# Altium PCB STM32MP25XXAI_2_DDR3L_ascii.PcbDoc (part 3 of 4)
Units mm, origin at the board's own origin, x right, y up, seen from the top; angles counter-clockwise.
Board outline 172 x 137 mm, 6 copper layers (Top Layer, Signal Layer 1, Signal Layer 2, Signal Layer 3, Signal Layer 4, Bottom Layer), stack 2.079 mm thick; 237 components, 152 nets, 1304 pads, 909 vias.
Unrouted connection lines stored in the file: 13.
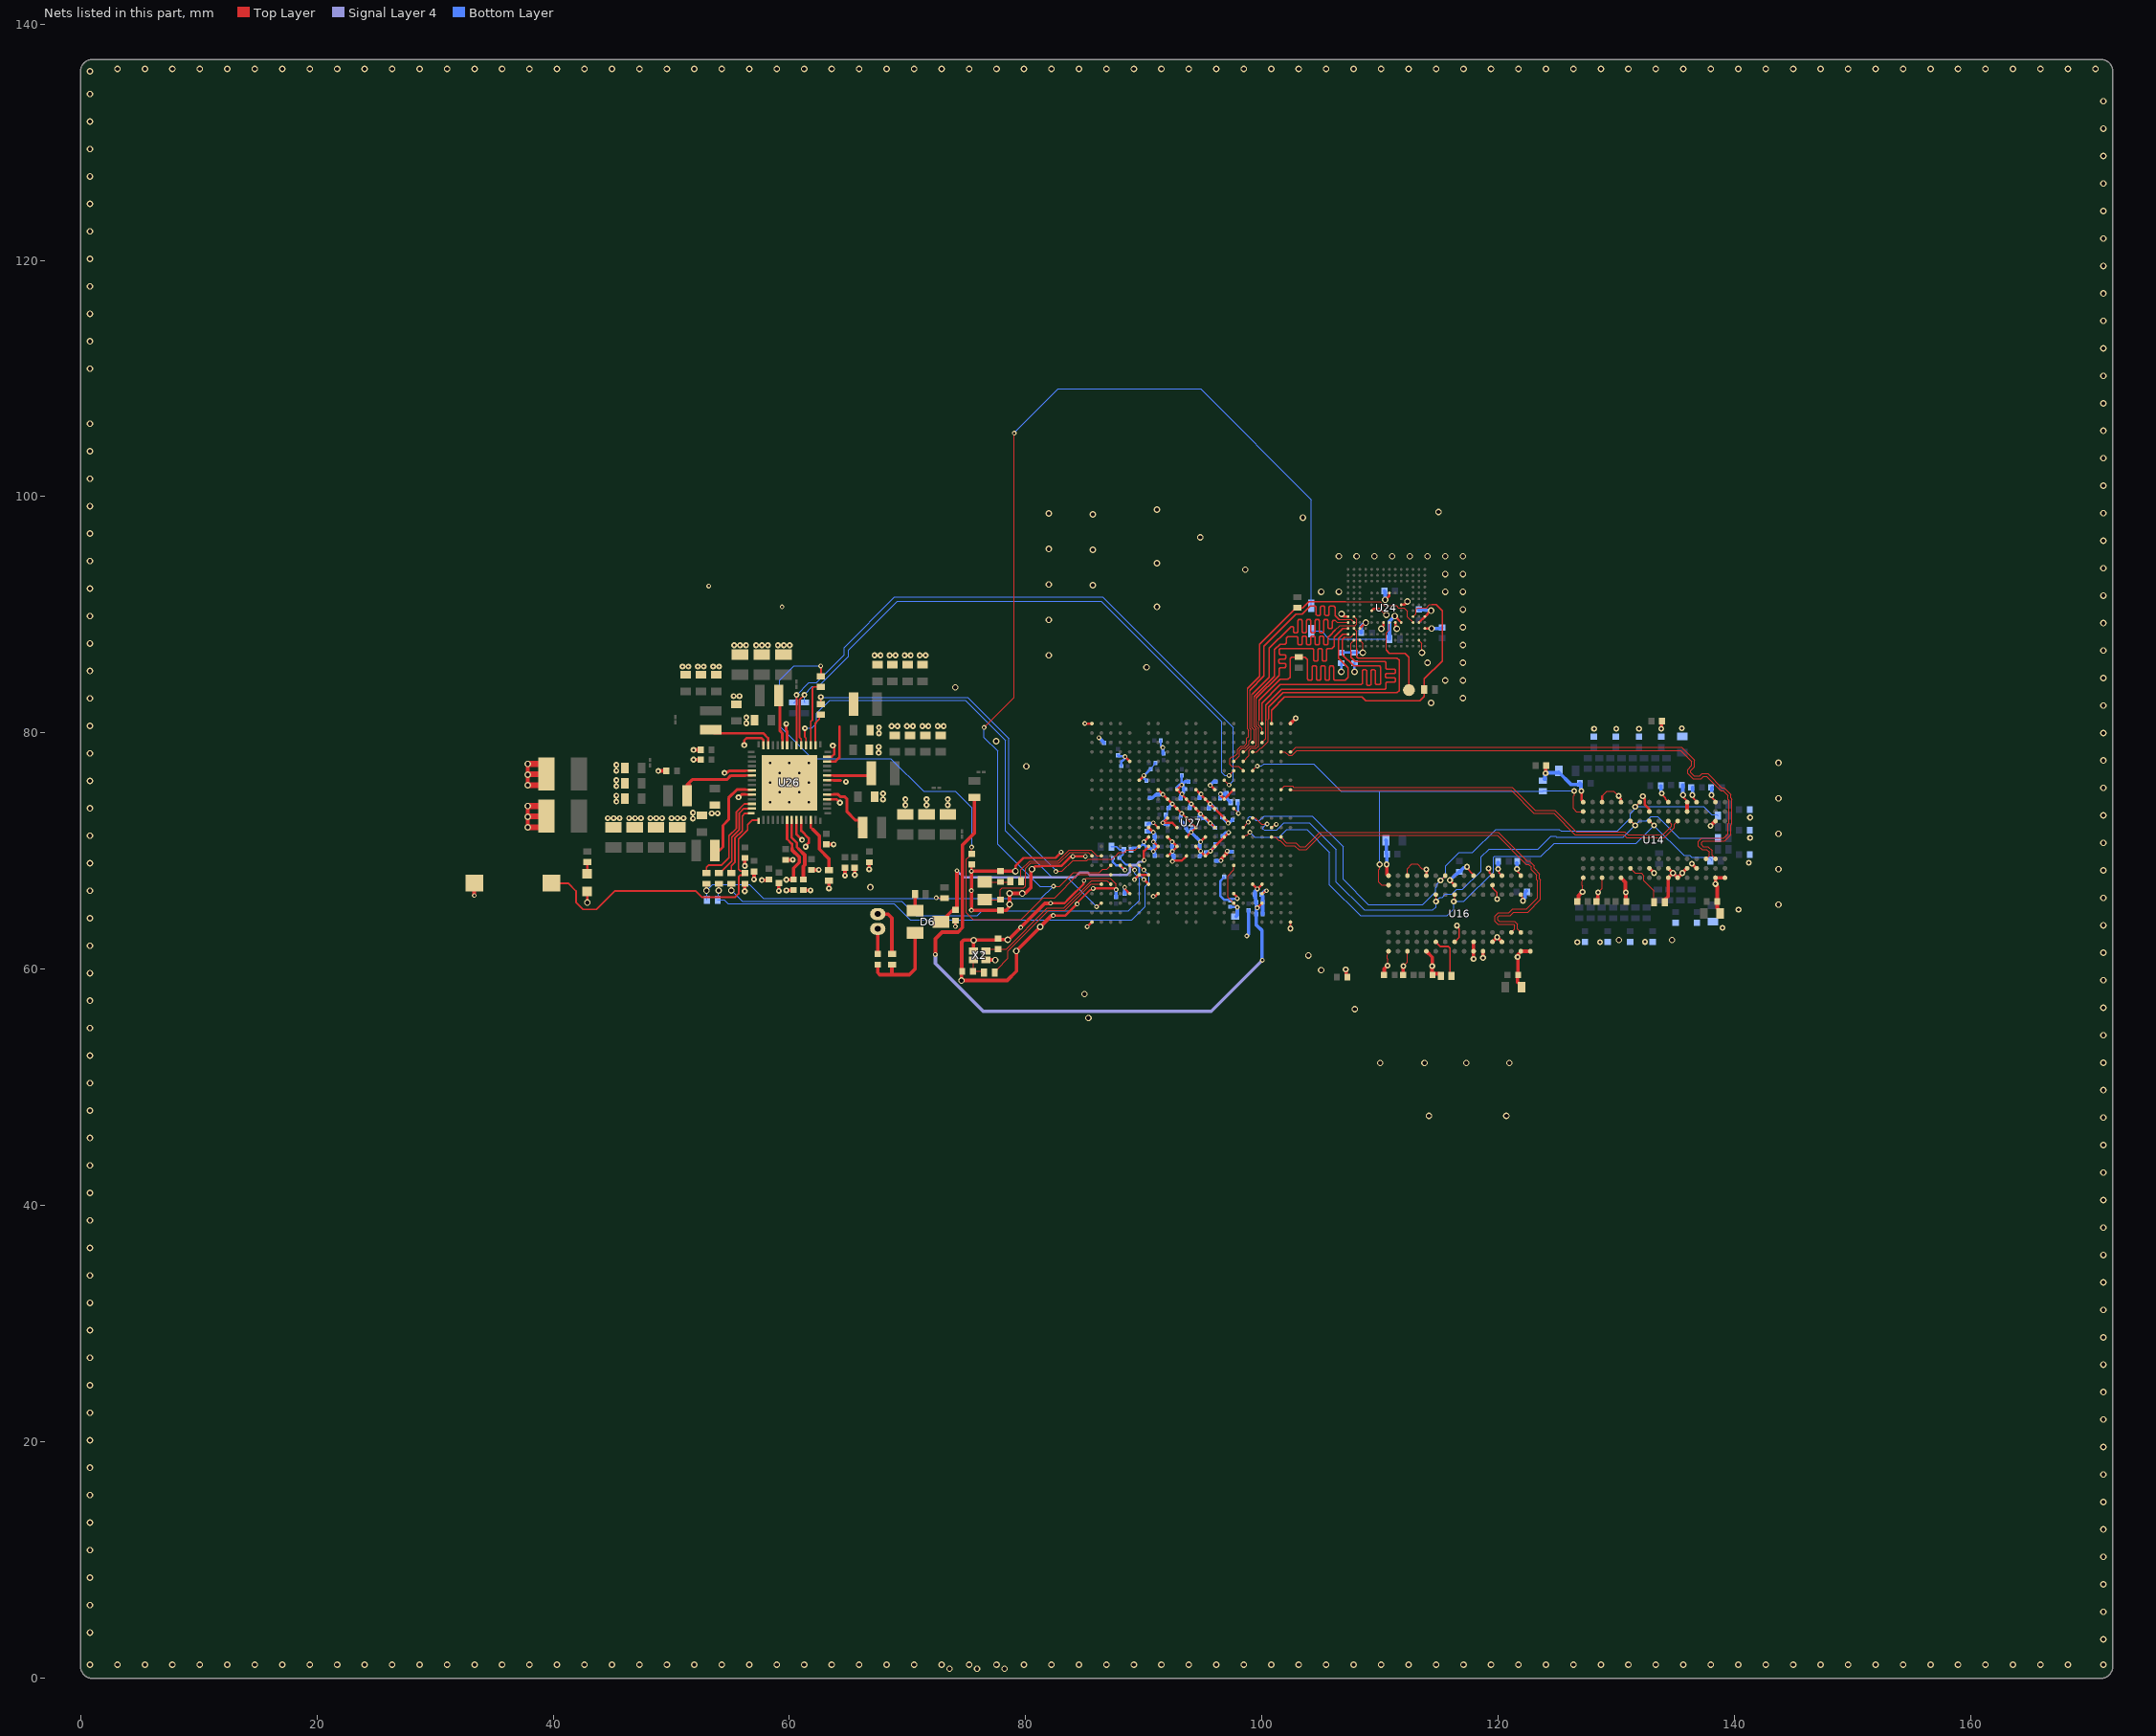
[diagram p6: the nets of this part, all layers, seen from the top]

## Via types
v1: diameter 0.55, hole 0.35, Top Layer to Bottom Layer, 421 vias
v2: diameter 0.4, hole 0.2, Top Layer to Bottom Layer, tented both sides, 169 vias
v3: diameter 0.5, hole 0.2, Top Layer to Bottom Layer, 146 vias
v4: diameter 0.5, hole 0.25, Top Layer to Bottom Layer, 145 vias
v5: diameter 0.4, hole 0.2, Top Layer to Bottom Layer, 28 vias

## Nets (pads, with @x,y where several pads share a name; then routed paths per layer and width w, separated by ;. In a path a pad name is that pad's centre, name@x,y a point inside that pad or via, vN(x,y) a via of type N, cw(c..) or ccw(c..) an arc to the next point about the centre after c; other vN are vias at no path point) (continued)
DDR_DQS1_N: U16.B7 U27.N21 | length 33.6
  Top Layer w0.09: U27.N21@101.6,71.2 101.6,71.18 102.065,70.715 102.862,70.715 103.202,70.375 103.669,70.375 104.875,71.581 120.005,71.581 122.441,69.145 122.643,69.145 123.02,68.767 123.02,68.542 123.482,68.08 123.482,67.668 123.56,67.59 123.56,65.922 122.486,64.848 121.302,64.848 120.99,64.536 120.08,64.536 119.948,64.404 119.948,64.168 120.062,64.054 121.388,64.054 121.631,63.811 121.631,63.396 U16.B7@121.901,63.126
DDR_DQS1_P: U16.C7 U27.N20 | length 34.1
  Top Layer w0.09: U27.N20@100.801,71.202 101.126,71.202 101.423,70.905 101.521,70.905 101.961,70.465 102.758,70.465 103.098,70.125 103.772,70.125 104.978,71.331 119.902,71.331 122.338,68.895 122.539,68.895 122.77,68.664 122.77,68.439 ; U16.C7@121.101,63.127 121.381,63.408 121.381,63.707 121.285,63.804 119.958,63.804 119.698,64.064 119.698,64.507 119.977,64.786 120.887,64.786 121.198,65.098 122.382,65.098 123.31,66.026 123.31,67.487 123.232,67.565 123.232,67.977 122.77,68.439
DDR_DQS2_N: U14.B7 U27.D22 | length 48.7
  Top Layer w0.09: U27.D22@102.4,78.4 102.464,78.4 102.846,78.782 135.508,78.782 136.603,77.687 136.603,77.138 136.277,76.812 136.277,76.659 136.573,76.363 137.063,76.363 137.261,76.561 137.729,76.561 138.92,75.37 139.117,75.37 139.677,74.81 139.677,74.489 139.77,74.396 139.77,72.304 139.677,72.211 139.677,71.369 139.167,70.859 137.315,70.859 137.19,70.735 137.19,70.539 137.333,70.396 137.731,70.396 138.091,70.036 138.091,69.637 U14.B7@138.376,69.352
DDR_DQS2_P: U14.C7 U27.D21 | length 49.2
  Top Layer w0.09: U27.D21@101.601,78.402 101.946,78.402 102.242,78.105 102.278,78.105 102.523,78.105 102.95,78.532 135.404,78.532 136.353,77.584 136.353,77.242 136.027,76.916 136.027,76.556 136.47,76.113 137.166,76.113 137.365,76.311 137.625,76.311 138.816,75.12 139.014,75.12 139.427,74.707 139.427,74.385 139.52,74.293 139.52,72.407 139.427,72.315 139.427,71.473 139.063,71.109 137.212,71.109 136.94,70.838 136.94,70.435 137.23,70.146 137.627,70.146 137.841,69.932 137.841,69.617 U14.C7@137.576,69.352
DDR_DQS3_N: U14.G3 U27.H21 | length 35.8
  Top Layer w0.09: U27.H21@101.601,75.202 101.601,75.227 101.876,75.502 102.565,75.502 102.675,75.392 121.179,75.392 123.11,73.461 124.776,73.461 126.587,71.65 130.702,71.65 130.967,71.385 133.937,71.385 134.652,72.1 134.652,72.286 134.387,72.552 U14.G3@134.376,72.552
DDR_DQS3_P: U14.F3 U27.H22 | length 35.2
  Top Layer w0.09: U27.H22@102.4,75.2 102.458,75.142 121.075,75.142 123.006,73.211 124.673,73.211 126.484,71.4 130.598,71.4 130.864,71.134 134.04,71.134 134.902,71.996 134.902,72.279 U14.F3@135.176,72.552
DDR_ODT: R159.1 U14.K1 U16.K1 U27.M17 | length 51.9
  Top Layer w0.09: U27.M17@98.4,72 98.4,72.013 98.825,72.438 v5(98.825,72.45) ; v4(115.1,67.525) U16.K1@115.5,67.925 ; v4(131.575,73.75) U14.K1@131.963,74.138
  Bottom Layer w0.09: v5(98.825,72.45) 98.825,72.81 98.936,72.921 99.132,72.921 99.463,72.59 99.794,72.59 100.184,72.98 104.258,72.98 106.865,70.373 106.865,67.626 108.996,65.495 113.609,65.495 114.695,66.581 114.695,66.899 114.79,66.994 114.79,67.188 115.1,67.498 v4(115.1,67.525) 115.555,67.98 115.555,68.755 116.683,69.883 117.809,69.883 119.776,71.85 125.151,71.85 125.299,71.702 130.073,71.702 131.18,72.809 131.18,73.164 131.497,73.48 131.497,73.698 131.576,73.777 137.351,73.777 138.041,73.087 138.488,73.087 R159.1@138.575,73
DDR_RASN: R168.1 U14.J3 U16.J3 U27.N17 | length 51.6
  Top Layer w0.09: U27.N17@98.4,71.2 98.457,71.2 98.62,71.363 98.738,71.363 v5(98.975,71.6) ; v4(116.226,65.75) 116.301,65.825 U16.J3@116.301,66.327 ; U14.J3@132.775,72.55 132.8,72.55 133.15,72.2 v4@133.175,72.2
  Bottom Layer w0.09: v5@98.975,71.592 99.386,71.181 101.446,71.181 102.085,71.82 103.778,71.82 105.705,69.893 105.705,67.146 108.316,64.535 115.654,64.535 116.226,65.106 v4(116.226,65.75) 117.075,65.75 119.571,68.247 119.571,69.486 119.665,69.58 123.618,69.58 124.714,70.676 131.651,70.676 133.145,72.17 v4(133.175,72.17) 135.695,69.65 136.2,69.65 136.345,69.505 137.865,69.505 138.075,69.295 R168.1@138.075,69.2
DDR_RESETN: R156.2 U14.T2 U16.T2 U27.F18 | length 39.5
  Top Layer w0.09: U27.F18@99.2,76.8 v5(99.6,77.2) ; v4(109.95,68.875) 109.95,68.501 109.876,68.427 109.876,67.379 110.128,67.127 U16.T2@110.701,67.127 ; v4(126.425,75.1) 126.425,74.726 126.351,74.652 126.351,73.604 126.603,73.352 U14.T2@127.176,73.352
  Bottom Layer w0.09: v5(99.6,77.2) 99.943,77.2 100.145,77.402 104.352,77.402 106.679,75.075 109.95,75.075 ; v4(109.95,68.875) 109.95,75.075 ; R156.2@123.75,75.075 109.95,75.075 ; R156.2@123.775,75.1 v4(126.425,75.1)
DDR_WEN: R163.1 U14.L3 U16.L3 U27.L18 | length 51.6
  Top Layer w0.09: U27.L18@99.2,72.8 99.44,72.8 99.94,72.3 v5(100.425,72.3) ; U16.L3@114.7,66.325 114.725,66.3 v4(114.725,65.75) ; U14.L3@131.175,72.55 131.2,72.55 v4@131.55,72.2
  Bottom Layer w0.09: v5(100.425,72.3) 100.37,72.3 100.076,72.006 100.076,71.881 100.176,71.781 101.226,71.781 101.845,72.4 104.018,72.4 106.285,70.133 106.285,67.386 108.656,65.015 114.455,65.015 114.723,65.283 v4@114.723,65.748 ; v4(114.725,65.75) 115.052,66.077 115.243,66.077 115.516,66.35 116.064,66.35 116.477,66.763 116.978,66.763 118.545,68.33 118.545,69.188 118.543,69.19 118.543,69.516 119.207,70.18 123.369,70.18 124.439,71.25 124.843,71.25 124.906,71.187 130.562,71.187 131.95,72.575 132.539,72.575 132.553,72.589 132.561,72.589 132.894,72.922 133.489,72.922 135.311,71.1 R163.1@138.575,71.1
  other v4: 131.575,72.17
eMMC.SDMMC2_CK: R49.1 U24.M6 U27.A20 | length 26
  Top Layer w0.09: U24.M6@112.775,89.85 113.025,90.1 113.025,90.454 113.171,90.6 113.925,90.6 114.175,90.85 114.375,90.85
  Top Layer w0.11: U27.A20@100.8,80.8 100.8,81.935 101.902,83.037 106.072,83.037 108.445,83.037 108.767,82.715 113.348,82.715 113.725,83.093 R49.1@113.725,83.685 113.725,84.582 115.25,86.107 115.25,90.35 114.75,90.85 114.375,90.85
eMMC.SDMMC2_CMD: R37.1 U24.M5 U27.F17 | length 28.4
  Top Layer w0.09: U27.F17@98.4,76.8 98.002,77.198 97.453,77.198 97.29,77.36 97.29,77.84 97.432,77.982 97.62,77.982 97.91,78.272 97.91,78.596 98.199,78.885 98.488,78.885 98.715,79.112 98.715,79.56 98.865,79.71 98.865,80.231 98.775,80.321 98.775,83.777 ; 107.071,91.1 109.975,91.1 110.3,90.775 111.35,90.775 111.525,90.6 112,90.6 112.3,90.3 112.3,89.825 U24.M5@112.775,89.35
  Top Layer w0.11: 98.775,83.777 99.787,84.789 99.787,87.507 102.287,90.007 102.88,90.6 R37.1@102.975,90.6 103.449,90.6 103.943,91.093 107.071,91.093
eMMC.SDMMC2_D0: R44.1 U24.A3 U27.B19 | length 25.9
  Top Layer w0.09: 99.75,81.05 99.695,80.995 99.695,80.674 100,80.369 U27.B19@100,80
  Top Layer w0.11: 99.75,81.05 99.75,82.762 101.528,84.541 102.178,84.541 102.363,84.725 102.363,86.308 102.482,86.428 R44.1@103.1,86.428 103.633,86.428 103.836,86.225 103.836,84.57 103.929,84.477 ; 103.932,84.474 103.929,84.477 ; U24.A3@107.275,88.35 106.824,88.35 106.475,88.001 106.475,86.332 107.27,85.537 107.27,84.724 107.023,84.477 106.406,84.477 106.162,84.477 106.071,84.568 106.071,85.579 105.98,85.67 105.798,85.67 105.707,85.579 105.707,84.566 105.616,84.475 105.434,84.475 105.343,84.566 105.343,85.593 105.252,85.684 105.07,85.684 104.979,85.593 104.979,84.566 104.888,84.475 104.706,84.475 104.615,84.566 104.615,85.593 104.524,85.684 104.342,85.684 104.251,85.593 104.251,84.568 104.16,84.477 104.105,84.477 103.929,84.477
eMMC.SDMMC2_D1: U24.A4 U27.E17 | length 24
  Top Layer w0.09: U27.E17@98.4,77.6 98.895,78.095 98.895,78.526 99.074,78.705 99.505,78.705 99.695,78.895 99.695,80.419 99.515,80.599 99.515,82.965 99.525,82.975
  Top Layer w0.11: 99.525,82.965 99.525,82.975 101.442,84.892 101.442,85.031 101.442,85.45 101.533,85.541 101.944,85.541 102.035,85.632 102.035,85.814 101.944,85.905 101.493,85.905 101.402,85.996 101.402,86.178 101.493,86.269 101.944,86.269 102.035,86.36 102.035,86.542 101.944,86.633 101.533,86.633 101.442,86.724 101.442,86.911 101.442,87.057 101.525,87.14 103.849,87.14 104.268,87.14 104.359,87.049 104.359,86.182 104.45,86.091 104.632,86.091 104.723,86.182 104.723,87.061 104.814,87.152 104.996,87.152 105.087,87.061 105.087,86.182 105.178,86.091 105.36,86.091 105.451,86.182 105.451,87.049 105.542,87.14 105.917,87.14 105.923,87.146 106.102,87.325 106.102,88.132 106.82,88.85 U24.A4@107.275,88.85
eMMC.SDMMC2_D2: U24.A5 U27.C18 | length 25.1
  Top Layer w0.09: 99.155,83.28 99.155,80.45 99.335,80.27 99.335,79.361 99.2,79.226 U27.C18@99.2,79.2 ; 106.195,89.516 106.353,89.358 107.267,89.358 U24.A5@107.275,89.35
  Top Layer w0.11: 99.165,83.28 100.606,84.721 100.606,87.166 102.247,88.807 102.446,89.006 102.575,89.006 102.666,88.915 102.666,88.55 102.757,88.459 102.939,88.459 103.03,88.55 103.03,89.502 103.121,89.593 103.303,89.593 103.394,89.502 103.394,88.55 103.485,88.459 103.667,88.459 103.758,88.55 103.758,89.502 103.849,89.593 104.031,89.593 104.122,89.502 104.122,88.55 104.213,88.459 104.395,88.459 104.486,88.55 104.486,89.502 104.577,89.593 104.759,89.593 104.85,89.502 104.85,88.55 104.941,88.459 105.123,88.459 105.214,88.55 105.214,89.502 105.305,89.593 105.487,89.593 105.578,89.502 105.578,88.917 105.669,88.826 105.851,88.826 105.942,88.917 105.942,89.425 106.033,89.516 106.103,89.516 106.195,89.516
eMMC.SDMMC2_D3: U24.B2 U27.C19 | length 23.8
  Top Layer w0.09: U27.C19@100,79.2 100.31,79.51 100.31,81.055 ; 107.525,86.9 107.525,87.6 U24.B2@107.775,87.85
  Top Layer w0.11: 100.31,81.055 100.299,81.065 100.299,82.373 101.646,83.72 110.396,83.72 110.461,83.784 110.461,83.796 110.461,84.215 110.552,84.306 111.194,84.306 111.285,84.397 111.285,84.579 111.194,84.67 110.539,84.67 110.448,84.761 110.448,84.943 110.539,85.034 111.194,85.034 111.285,85.125 111.285,85.307 111.194,85.398 110.552,85.398 110.461,85.489 110.461,85.916 110.461,85.974 110.396,86.038 107.887,86.038 107.525,86.4 107.525,86.9
eMMC.SDMMC2_D4: U24.B3 U27.A19 | length 24.7
  Top Layer w0.09: 107,88.1 107.525,88.1 U24.B3@107.775,88.35
  Top Layer w0.11: U27.A19@100,80.8 100,82.538 101.546,84.084 108.332,84.084 108.387,84.084 108.478,84.175 108.478,85.263 108.569,85.354 108.751,85.354 108.842,85.263 108.842,84.122 108.933,84.031 109.115,84.031 109.206,84.122 109.206,85.263 109.297,85.354 109.479,85.354 109.57,85.263 109.57,84.175 109.661,84.084 109.866,84.084 109.947,84.084 110.053,84.19 110.053,85.549 109.938,85.664 107.753,85.664 106.814,86.603 106.814,87.914 107,88.1
eMMC.SDMMC2_D5: U24.B4 U27.D18 | length 25
  Top Layer w0.09: U27.D18@99.2,78.4 99.562,78.4 99.872,78.71 99.948,78.71 100.49,79.252 100.51,79.272 100.51,81.16 100.55,81.2 ; U24.B4@107.775,88.85 108.025,88.6 108.025,87.75 108.025,87.15
  Top Layer w0.11: 100.55,81.2 100.55,82.184 101.775,83.409 106.072,83.409 111.428,83.409 111.596,83.577 111.596,86.171 111.422,86.345 108.142,86.345 108.025,86.462 108.025,87.15
eMMC.SDMMC2_D6: U24.B5 U27.E16 | length 23.9
  Top Layer w0.09: U27.E16@97.6,77.6 98.09,78.09 98.09,78.375 98.095,78.38 98.095,78.526 98.274,78.705 98.563,78.705 98.895,79.037 98.895,79.345 99.045,79.495 99.045,80.305 98.965,80.385 98.965,83.61 ; 106.499,89.612 106.803,89.612 106.815,89.6 107.525,89.6 U24.B5@107.775,89.35
  Top Layer w0.11: 98.975,83.625 100.173,84.823 100.173,87.357 102.876,90.06 103.393,90.06 104.072,90.739 104.491,90.739 104.582,90.648 104.582,90.022 104.673,89.931 104.855,89.931 104.946,90.022 104.946,90.659 105.037,90.75 105.219,90.75 105.31,90.659 105.31,90.022 105.401,89.931 105.583,89.931 105.674,90.022 105.674,90.648 105.765,90.739 106.071,90.739 106.179,90.63 106.195,90.615 106.195,89.916 106.499,89.612
eMMC.SDMMC2_D7: U24.B6 U27.D17 | length 24
  Top Layer w0.09: U27.D17@98.4,78.4 98.44,78.44 98.552,78.44 98.997,78.885 99.431,78.885 99.515,78.969 99.515,80.345 99.335,80.525 99.335,83.11 ; 106.195,88.716 106.579,89.1 107.879,89.1 108.025,89.246 108.025,89.6 U24.B6@107.775,89.85
  Top Layer w0.11: 99.355,83.11 101.049,84.804 101.049,87.051 101.524,87.526 101.95,87.525 102.049,87.624 102.049,88.051 102.171,88.172 102.52,88.172 102.939,88.172 103.03,88.081 103.03,87.56 103.121,87.469 103.303,87.469 103.394,87.56 103.394,88.107 103.485,88.198 103.667,88.198 103.758,88.107 103.758,87.56 103.849,87.469 104.031,87.469 104.122,87.56 104.122,88.107 104.213,88.198 104.395,88.198 104.486,88.107 104.486,87.56 104.577,87.469 104.759,87.469 104.85,87.56 104.85,88.107 104.941,88.198 105.123,88.198 105.214,88.107 105.214,87.56 105.305,87.469 105.487,87.469 105.578,87.56 105.578,88.099 105.726,88.247 106.195,88.716
GND: B2.1 C1.2 C2.1 C3.1 C4.2 C5.1 C6.1 C7.1 C8.1 C9.1 C10.1 C11.2 C12.1 C13.2 C14.1 C15.1 C16.2 C17.1 C18.2 C19.1 C20.1 C21.1 C22.1 C23.1 C24.1 C25.1 C26.1 C27.1 C28.1 C29.1 C30.1 C31.1 C32.1 C33.1 C34.1 C35.1 C36.1 C37.1 C38.1 C39.1 C40.1 C41.1 C42.2 C43.1 C44.2 C45.1 C46.1 C47.2 C48.1 C52.1 C53.1 C54.2 C55.1 C56.1 C57.1 C58.1 C59.1 C60.1 C61.1 C62.1 C63.1 C64.1 C65.1 C66.1 C67.1 C68.1 C69.1 C70.1 C71.1 C72.1 C73.1 C74.1 C75.1 C76.1 C77.1 C79.1 C80.1 C81.2 C86.2 C87.1 C89.1 C90.1 C91.2 C92.2 C96.1 C97.1 C98.1 C130.1 C131.1 C132.1 C133.1 C134.1 C140.1 C141.2 C142.2 C143.1 C146.1 C147.1 C148.1 C149.1 C152.1 C153.1 C154.1 C155.1 C156.1 C157.1 C159.1 C172.1 C173.1 C177.1 C178.1 C179.1 C180.1 C181.1 C182.1 C183.1 C184.1 C185.1 C186.1 C187.1 C188.1 C189.1 C190.2 C191.1 C192.1 C193.1 C194.1 C199.1 C200.1 C201.1 C202.1 C204.1 C205.1 C206.1 C207.1 C208.2 C209.1 C212.1 C217.2 C234.1 C275.1 C285.1 C302.1 C304.1 C306.1 C307.1 C360.1 C361.1 C362.1 C363.1 C364.1 C367.1 C373.1 C374.1 C375.1 C384.1 C390.1 C399.1 LD11.2 R57.1 R68.1 R83.1 R156.1 R262.1 U14.A9 U14.B1 U14.B3 U14.B9 U14.D1 U14.D8 U14.E1 U14.E2 U14.E8 U14.F9 U14.G1 U14.G8 U14.G9 U14.J2 U14.J8 U14.M1 U14.M9 U14.P1 U14.P9 U14.T1 U14.T9 U16.A9 U16.B1 U16.B3 U16.B9 U16.D1 U16.D8 U16.E1 U16.E2 U16.E8 U16.F9 U16.G1 U16.G8 U16.G9 U16.J2 U16.J8 U16.M1 U16.M9 U16.P1 U16.P9 U16.T1 U16.T9 U24.A6 U24.C4 U24.E7 U24.G5 U24.H10 U24.J5 U24.K8 U24.N2 U24.N5 U24.P4 U24.P6 U26.9 U26.10 U26.18 U26.22 U26.27 U26.36 U26.41 U26.47 U26.52 U26.57 U27.A1 U27.A22 U27.AB1 U27.AB22 U27.E5 U27.G6 U27.H8 U27.H10 U27.H12 U27.H14 U27.H16 U27.J9 U27.J11 U27.J13 U27.J15 U27.K10 U27.K12 U27.K14 U27.L9 U27.L11 U27.L13 U27.L15 U27.M7 U27.M10 U27.M12 U27.M14 U27.M20 U27.N7 U27.N9 U27.N11 U27.N13 U27.N15 U27.P8 U27.P10 U27.P12 U27.P14 U27.R9 U27.R11 U27.R13 U27.R15 U27.T4 U27.U6 U27.U7 U27.W5 U27.W8 U27.W16 U27.W19 X2.2 X2.4 | length 272.9
  Top Layer w0.09: v2(84.925,67.5) 85.12,67.695 87.155,67.695 87.183,67.667 87.65,67.2 v2(87.65,66.75) ; U27.M20@100.8,72 100.849,72 101.124,72.275 v5(101.2,72.275) ; v4(111.95,60.275) 112.3,60.625 U16.P9@112.3,61.525 ; U16.P1@112.3,67.925 112.3,68.525 112.676,68.9 113.138,68.9 113.515,68.523 113.828,68.523 v4(113.9,68.45) ; U24.N2@113.275,87.85 113.525,87.6 v1(113.525,86.8) ; U16.B9@121.9,61.525 U16.B9@121.904,61.525 ; v4(128.425,66.5) 128.775,66.85 U14.P9@128.775,67.75 ; R68.1@134.075,65.775 R68.1@134.285,65.985 ; U14.B9@138.376,67.752 U14.B9@138.378,67.75
  Top Layer w0.1: v3@44.624,72.799 v3@44.625,72.8 ; X2.2@75.547,61.575 X2.2@75.548,61.576 ; v1@75.573,62.448 v1(75.587,62.462) v1@75.6,62.475 ; v4(110.625,60.323) 110.625,60.859 110.583,60.9 110.583,61.199 110.653,61.268 110.653,61.477 U16.T9@110.7,61.525 ; C360.1@126.701,65.852 C360.1@126.774,65.925 ; v4(127.125,66.55) 127.125,67.058 127.075,67.109 127.075,67.44 127.125,67.491 127.125,67.7 U14.T9@127.175,67.75 ; 128.775,74.642 128.775,74.649 129.201,75.075 129.772,75.075 v4(130.173,74.674)
  Top Layer w0.15: v2(84.345,65.531) 84.345,65.598 84.448,65.702 84.448,65.708 85.465,66.725 85.523,66.725 85.636,66.838 v2(85.703,66.838) ; v4@111.932,60.358 v4@111.951,60.377 ; U16.J8@116.301,62.327 116.675,62.701 116.675,63.43 116.5,63.605 v4(116.5,63.7) ; v4@117.35,68.625 117.35,68.536 117.8,68.086 117.8,68.079 117.901,67.979 U16.G1@117.901,67.927 ; v4@119.175,68.5 119.238,68.438 119.238,68.19 U16.E1@119.501,67.927 ; U16.E2@119.501,67.127 119.513,67.115 119.513,66.873 119.876,66.51 119.876,65.999 v4@119.9,65.975 ; v4(119.975,68.5) 120.038,68.438 120.038,68.19 U16.D1@120.301,67.927 ; v4(121.575,68.5) 121.642,68.433 121.642,68.251 121.9,67.993 U16.B1@121.9,67.925 ; U16.B3@121.901,66.327 121.901,66.257 122.016,66.142 122.016,65.854 v4@122.088,65.782 ; v4@133.8,74.875 133.8,74.852 134.132,74.52 134.132,74.429 134.25,74.311 134.25,74.304 134.351,74.204 U14.G1@134.351,74.152 ; v4@135.625,74.725 135.692,74.658 135.692,74.496 135.975,74.213 U14.E1@135.975,74.15 ; v4@136.425,74.725 136.492,74.658 136.492,74.499 136.775,74.216 U14.D1@136.775,74.15 ; v4@138.025,74.725 138.092,74.658 138.092,74.496 138.375,74.213 U14.B1@138.375,74.15
  Top Layer w0.2: v1(42.887,65.648) LD11.2@42.887,66.577 ; U26.27@63.17,78 63.579,78 63.77,78.191 63.77,78.91 v3@63.816,78.956 ; v3(63.67,78.93) v3@63.727,78.873 ; C87.1@74.05,64.125 74.05,63.634 v2(74.051,63.633) ; v2(75.402,68.305) 75.416,68.319 C33.1@75.416,68.915 ; v1(79.125,68.3) 79.125,68.75 79.8,69.425 82.507,69.425 v2(83.002,69.92) ; v1(80.525,68.475) 80.568,68.475 80.818,68.725 81.262,68.725 81.287,68.75 83.012,68.75 83.784,69.522 83.94,69.522 v2(83.978,69.56) v2(85.046,69.56) ; v2(82.1,65.6) 83.28,65.6 83.703,66.023 84.887,67.207 84.887,67.462 v2(84.925,67.5) ; v2(82.325,64.55) 83.364,64.55 v2(84.345,65.531) ; v2(85,80.805) 85.005,80.8 U27.A1@85.6,80.8 ; v2(85.2,63.6) U27.AB1@85.6,64 ; v2(85.703,66.838) 87.508,66.838 87.596,66.75 v2(87.65,66.75) ; U27.T4@88,68.8 v2(88.4,68.4) ; v2(88.37,66.944) 88.408,66.905 88.408,66.792 U27.W5@88.8,66.4 ; v2(88.4,78) U27.E5@88.8,77.6 ; v2(89.2,67.6) U27.U6@89.6,68 U27.U7@90.4,68 ; U27.G6@89.6,76 v2(90,76.4) ; v2(90,70.8) U27.N7@90.4,71.2 ; v2(90.788,66.173) 90.827,66.211 90.984,66.211 91.173,66.4 U27.W8@91.2,66.4 ; v2@90.8,70 U27.P8@91.2,70.4 v2(90.8,70.8) ; U27.H8@91.2,75.2 v2(91.6,74.8) U27.J9@92,74.4 v2(92.4,74) v2@93.225,73.175 ; U27.R9@92,69.6 92.025,69.6 v2(92.4,69.975) 92.8,70.375 U27.P10@92.8,70.4 92.4,70.8 U27.N9@92,71.2 ; U27.L9@92,72.8 v2(91.6,72.4) 92.4,72.4 U27.M10@92.8,72 ; v2@92.454,69.1 92.4,69.1 92.5,69.2 93.2,69.2 U27.R11@93.6,69.6 ; v2(93.2,73.175) v2@93.225,73.175 ; v2(93.201,75.6) 92.801,75.2 v2@93.226,74.775 ; v2(93.226,74.85) v2@93.226,74.775 ; U27.N11@93.6,71.2 v2(94,71.6) U27.M12@94.4,72 v2@93.225,73.175 ; U27.P12@94.4,70.4 v2(94.8,70) U27.R13@95.2,69.6 95.787,70.188 ; U27.H12@94.407,75.2 94.757,74.85 v2(94.832,74.85) 94.832,74.775 v2(95.607,74) U27.L15@96.807,72.8 ; v2(94.8,70.8) U27.N13@95.2,71.2 ; v2@95.625,75.575 U27.H14@96,75.2 ; U27.P14@96,70.4 95.787,70.188 ; U27.M14@96,72 95.626,72.375 94.851,73.15 v2(94.801,73.15) 94.801,73.2 v2(94.001,74) v2@93.226,74.775 ; v2(96.475,74.85) 96.514,74.812 96.514,74.686 U27.J15@96.8,74.4 U27.H16@97.6,75.2 ; U27.L15@96.8,72.8 97.087,72.513 97.087,72.413 v2(97.125,72.375) ; v2(97.175,71.575) 95.787,70.188 ; U27.W16@97.6,66.4 97.862,66.138 97.862,66.038 v2(97.9,66) ; U27.W19@100,66.4 100.027,66.4 100.239,66.612 100.337,66.612 v2(100.375,66.65) ; v4(102.4,63.45) U27.AB22@102.4,64 ; v1(106.725,90.075) 106.95,89.85 U24.A6@107.275,89.85 ; U24.C4@108.275,88.85 108.725,89.3 108.735,89.3 v1(108.775,89.34) ; U24.E7@109.275,90.35 109.426,90.501 110.011,90.501 110.516,89.995 v1(110.525,89.995) ; v1(110.1,88.825) 110.1,88.913 110.275,89.088 U24.G5@110.275,89.35 ; v1(110.425,91.275) 110.775,91.625 U24.H10@110.775,91.85 ; U24.J5@111.275,89.35 111.275,89.045 111.4,88.92 v1(111.4,88.825) ; U24.K8@111.775,90.85 112.025,90.85 v1(112.3,91.125) ; U24.N5@113.275,89.35 U24.P6@113.775,89.85 114.275,90.35 v1(114.3,90.35) ; U24.P4@113.775,88.85 v1(114.35,88.85) ; U16.M1@113.901,67.927 113.939,67.965 113.939,68.273 114.001,68.334 114.001,68.399 113.95,68.45 v4(113.9,68.45) ; v4@115.9,67.528 v4@115.9,67.535 ; v4@115.9,67.575 v4(115.9,67.545) v4@115.9,67.535 ; U16.J2@116.3,67.125 116.3,67.135 v4@115.9,67.535 ; v4@117.897,60.892 v4@117.899,60.894 ; U16.G9@117.899,61.523 U16.G9@117.9,61.525 ; v4(127.025,75.1) 127.025,74.333 127.175,74.183 U14.T1@127.175,74.15 ; U14.P1@128.775,74.15 128.775,74.642 ; v4(130.173,74.674) 130.173,74.593 130.346,74.419 130.346,74.182 U14.M1@130.375,74.15 ; v4@132.15,74.644 132.375,74.419 132.375,73.956 132.737,73.595 132.737,73.388 U14.J2@132.775,73.35
  Top Layer w0.21: v3(56.175,78.975) 56.175,79.375 56.38,79.58 57.609,79.58 57.8,79.389 U26.41@57.8,78.97 ; 56.275,74.8 U26.52@56.83,74.8 ; 56.275,76.8 U26.47@56.83,76.8 ; U26.36@59.8,78.97 59.8,79.525 ; U26.9@60.6,72.63 60.6,71.42 v3(61.068,70.952) ; U26.10@61,72.63 61,71.734 61.635,71.099 61.635,70.72 61.37,70.456 v3(61.37,70.377) ; U26.18@63.17,74.4 63.972,74.4 v3(64.272,74.1) ; U26.22@63.17,76 63.725,76
  Top Layer w0.25: v3(54.508,76.625) 54.556,76.673 54.757,76.673 54.884,76.8 56.275,76.8 ; v3(55.687,74.563) 55.721,74.563 55.959,74.8 56.275,74.8 ; v3(59.725,80.775) 59.725,80.214 59.8,80.139 59.8,79.525 ; 63.725,76 64.33,76 ; v3@64.257,74.1 v3(64.272,74.1)
  Top Layer w0.275: U14.J8@132.775,68.55 v4@133.15,68.175 ; U14.G9@134.376,67.752 v4@134.776,68.152 ; U14.G8@134.376,68.552 134.376,68.551 134.774,68.152 134.776,68.152 U14.F9@135.176,67.752 ; U14.F9@135.176,67.766 135.183,67.766 135.582,68.164 135.582,68.171 U14.E8@135.962,68.552 ; v4@136.35,68.95 136.363,68.95 136.773,68.54 U14.D8@136.776,68.54
  Top Layer w0.3: v2(33.319,66.245) 33.324,66.25 33.324,67.279 B2.1@33.34,67.295 ; v1(37.848,72.014) v1(37.848,72.914) v1(37.848,73.814) ; v1(37.848,75.576) v1(37.848,76.476) v1(37.848,77.376) ; v3(48.895,76.79) C43.1@49.555,76.79 ; v3(51.885,77.75) C40.1@52.495,77.75 ; v3(51.885,78.575) C39.1@52.495,78.575 ; v3@56.225,68.81 C217.2@56.225,69.42 ; v3@56.227,66.58 C155.1@56.227,67.185 ; v3(57,67.61) C154.1@57,68.215 ; v3(57.665,67.55) C142.2@58.275,67.55 ; v3@59.1,66.69 C141.2@59.1,67.3 ; C153.1@59.675,69.27 v3(60.285,69.27) ; v3(59.74,66.68) C91.2@60.35,66.68 ; C208.2@61.175,66.68 v3(61.785,66.68) ; C209.1@61.85,68.42 v3(62.485,68.42) ; C156.1@63.125,70.57 v3(63.735,70.57) ; v3(63.35,66.84) R57.1@63.35,67.5 ; v3(64.7,67.93) C189.1@64.7,68.59 ; v3(65.525,67.99) C188.1@65.525,68.59 C188.1@65.525,68.65 ; v3@66.75,68.465 66.747,68.467 66.747,69.063 C190.2@66.75,69.065 ; C92.2@74.563,59.875 74.563,59.087 74.588,59.063 78.438,59.063 79.225,59.85 79.225,61.525 v1(79.2,61.55) 81.225,63.575 v1(81.225,63.6) 82.156,64.531 82.306,64.531 v2(82.325,64.55) ; C92.2@74.625,59.825 74.576,59.874 74.576,62.299 74.752,62.475 75.6,62.475 76,62.475 76.013,62.488 76.663,62.488 76.675,62.475 77.5,62.475 77.625,62.6 C90.1@77.65,62.6 77.736,62.514 v1@78.475,62.514 ; v2(75.4,65) C86.2@77.85,65 ; 75.4,65.275 v2@75.4,66.65 ; v2@75.4,68.3 v2@75.402,68.3 ; v2(75.402,66.655) v2@75.402,68.3 ; v2(75.402,68.305) v2@75.402,68.3 ; X2.2@75.573,61.551 v1@75.573,62.448 ; X2.4@76.66,60.788 76.667,60.794 77.408,60.794 v1(77.415,60.788) ; C86.2@77.955,65.105 C86.2@77.85,65 ; v1(78.475,62.5) 78.525,62.5 v2(79.575,63.55) 81.606,65.581 v2@82.081,65.581 ; v1(79.125,68.3) C81.2@77.85,68.3 v2@75.402,68.3 ; v1(80.525,68.475) 80.43,68.38 80.43,66.905 79.993,66.468 79.748,66.468 v1(79.7,66.42) 79.695,66.425 v1(78.625,66.425) v1(78.625,65.5) 78.578,65.452 78.578,65.239 78.339,65 C86.2@77.85,65 ; U27.M7@90.4,72 v2(90.8,71.6) ; v2(96.525,69.2) 96.544,69.219 96.544,69.344 U27.R15@96.8,69.6 96.975,69.775 96.975,69.898 97.05,69.973 v2(97.05,70) ; U27.A22@102.4,80.8 U27.A22@102.4,80.8 102.785,81.184 102.785,81.185 v4(102.85,81.25) ; v4(107.075,59.998) 107.075,59.944 107.12,59.898 107.12,59.455 C77.1@107.225,59.35 ; C373.1@110.298,59.698 110.33,59.73 110.33,60.047 110.606,60.323 v4(110.625,60.323) ; v4(110.55,68.875) 110.55,68.089 110.7,67.939 U16.T1@110.7,67.925 ; C374.1@111.851,59.627 111.932,59.708 v4@111.932,60.358 ; U16.M9@113.901,61.527 113.901,61.524 114.4,61.025 v4(114.4,60.275) 114.388,60.263 114.388,59.664 114.351,59.627 114.976,59.627 R83.1@115.051,59.552 ; v4@117.899,60.894 U16.G9@117.899,61.523 ; U16.G9@117.9,61.525 U16.G8@117.901,62.34 ; v4@118.701,61.052 U16.F9@118.701,61.527 ; U16.E8@119.5,62.325 v4(119.9,62.725) U16.D8@120.3,62.325 ; v4@121.563,68.512 v4(121.575,68.5) ; C80.1@121.95,58.5 121.95,58.625 121.78,58.795 121.735,58.795 121.625,58.905 121.625,59.625 121.657,59.656 121.657,60.994 121.638,61.013 121.676,61.051 121.676,61.274 121.904,61.502 121.904,61.525 U16.A9@122.7,61.525 ; v4@124.013,76.613 v4(124,76.6) v4@124.013,76.613 ; v4@124.038,76.638 v4@124.013,76.613 ; C48.1@124.05,77.25 124.013,77.213 v4@124.013,76.613 ; C360.1@126.774,65.925 126.774,66.223 v4@127.101,66.55 ; C361.1@128.301,65.852 128.377,65.852 128.405,65.88 128.405,66.036 128.425,66.056 v4(128.425,66.5) ; U14.M9@130.375,67.75 130.376,67.735 130.75,67.361 130.75,66.5 130.788,66.463 C362.1@130.788,65.965 ; C362.1@130.825,65.75 C362.1@130.85,65.775 ; C362.1@130.825,65.85 C362.1@130.862,65.813 ; v4@133.775,74.9 v4@133.8,74.875 ; v4(133.775,80.35) 133.812,80.387 133.812,80.962 C367.1@133.85,81 ; R68.1@134.075,65.775 134.075,65.87 134.375,66.17 U14.G9@134.375,67.75 ; U14.F9@135.176,67.752 U14.F9@135.176,67.766 ; v4@135.6,74.75 v4@135.625,74.725 ; U14.E2@135.975,73.35 U14.E1@135.975,74.128 ; v4@136.425,74.725 v4(136.425,74.75) ; v4@137.95,72.15 137.963,72.15 138.363,72.55 U14.B3@138.375,72.55 ; v4@138.025,74.725 v4@138.062,74.763 ; U14.B9@138.376,67.752 U14.B9@138.39,67.752 ; C364.1@138.776,64.827 138.776,64.952 138.773,64.952 138.525,65.2 138.525,67.021 138.375,67.171 v4(138.375,67.225) U14.B9@138.375,67.75 138.378,67.75 U14.A9@139.175,67.75 ; U14.A9@139.162,67.752 U14.A9@139.176,67.752
  Top Layer w0.5: v1(37.848,72.014) 39.39,72.014 C18.2@39.437,72.061 ; v1(37.848,72.914) 37.862,72.914 37.909,72.961 C18.2@39.437,72.961 ; v1(37.848,73.814) C18.2@39.379,73.814 ; v1(37.848,75.576) 39.39,75.576 C42.2@39.437,75.623 ; v1(37.848,76.476) 37.862,76.476 37.909,76.523 C42.2@39.437,76.523 ; v1(37.848,77.376) C42.2@39.379,77.376
  Bottom Layer w0.1: C73.1@90.575,76.925 90.7,77.05 90.7,77.13 90.85,77.28 90.85,77.35 C66.1@90.9,77.4 ; C212.1@91.86,73.1 92.032,73.272 92.032,73.582 C3.1@92.1,73.65 ; C10.1@92.35,70.327 C10.1@92.35,70.45
  Bottom Layer w0.15: C143.1@126.951,75.752 C143.1@127.076,75.627
  Bottom Layer w0.2: C75.1@87.375,69.425 87.375,69.075 87.65,68.8 87.9,68.8 88.3,68.4 v2(88.4,68.4) ; C70.1@87.8,78.1 87.862,78.038 88.362,78.038 v2(88.4,78) 88.405,77.996 88.405,77.854 88.205,77.655 88.18,77.655 88.163,77.655 88.075,77.567 C275.1@88.075,77.2 ; C79.1@88.9,70.125 89.075,70.3 89.625,70.3 89.962,70.636 89.962,70.761 v2(90,70.8) 90.038,70.761 90.038,70.522 C234.1@90.275,70.285 ; v2@89.988,76.388 90.038,76.338 90.038,76.137 C69.1@90.205,75.97 ; v2(90,76.4) 90.525,76.925 C73.1@90.575,76.925 ; C66.1@90.9,77.4 C66.1@90.975,77.475 ; C97.1@91.425,79.375 91.425,78.955 91.6,78.781 v2(91.6,78.775) ; v2(93.201,75.6) C71.1@93.201,76.4 ; C11.2@95.25,69.9 95.312,69.962 95.587,69.962 v2(95.625,70) ; C89.1@96.75,67.8 96.75,67.75 96.45,67.45 96.45,66.225 96.775,65.9 97.3,65.9 97.35,65.95 97.444,65.95 97.456,65.962 97.721,65.962 97.862,65.962 v2(97.9,66) ; v2@100.231,66.631 v2@100.356,66.631 ; v1(106.7,85.175) C181.1@106.7,85.9 ; v1(107.825,85.175) C182.1@107.825,85.9 ; C192.1@116.43,68.075 C192.1@116.5,68.075
  Bottom Layer w0.3: v2(86.194,79.6) 86.2,79.6 C98.1@86.625,79.175 ; C67.1@87.65,66.095 v2(87.65,66.75) ; v2(88.37,66.944) 88.375,66.938 C68.1@88.375,66.4 ; C234.1@90.275,70.285 90.3,70.26 90.549,70.26 90.781,70.028 90.781,69.994 v2(90.8,69.975) ; C61.1@90.317,71.688 90.367,71.638 90.735,71.638 90.773,71.6 v2(90.8,71.6) 90.8,71.573 90.9,71.473 90.9,71.225 C52.1@90.925,71.2 90.925,70.925 v2(90.8,70.8) 90.925,70.675 C47.2@90.925,70.388 90.925,70.1 v2(90.8,69.975) ; C74.1@90.5,74.5 90.725,74.5 91.025,74.8 C6.1@91.2,74.8 v2(91.6,74.8) ; C44.2@90.925,69.6 90.925,69.85 v2(90.8,69.975) ; C72.1@91.6,78.25 v2@91.6,78.775 ; 91.86,72.925 91.86,72.687 91.6,72.427 v2(91.6,72.4) 91.725,72.275 C46.1@92.025,72.275 ; C3.1@92.1,73.65 92.1,73.7 v2(92.4,74) ; C10.1@92.35,70.327 92.381,70.296 92.381,70.021 92.4,70.002 v2(92.4,69.975) ; C10.1@92.35,70.45 92.375,70.475 92.375,70.748 92.4,70.773 v2@92.4,70.8 ; v2@92.4,69.948 92.425,69.923 92.425,69.605 C45.1@92.475,69.555 ; v2@92.525,69.216 C45.1@92.525,69.6 ; C4.2@92.825,75.25 92.825,75.4 93.025,75.6 v2(93.201,75.6) ; C5.1@93.101,74.475 93.101,74.725 93.351,74.975 93.351,75.45 v2(93.201,75.6) ; v2(93.2,73.175) 93.175,73.175 93.1,73.1 C1.2@93.1,72.825 93.1,72.55 93.225,72.425 93.304,72.425 93.45,72.279 93.45,72.2 93.575,72.075 C9.1@93.575,72 ; 93.65,71.775 93.825,71.6 v2(94,71.6) ; C17.1@93.775,75.875 93.476,75.875 v2(93.201,75.6) ; C2.1@93.876,73.65 93.876,73.875 v2(94.001,74) ; C7.1@94.125,72 94,71.875 v2(94,71.6) ; C31.1@94.675,72.775 95.201,72.775 v2(95.601,72.375) 95.625,72.375 C57.1@96.026,71.974 ; C31.1@94.676,72.825 94.676,73.075 94.751,73.15 v2(94.801,73.15) ; C14.1@94.7,74.48 94.7,74.718 v2(94.832,74.85) ; C12.1@94.75,69.575 94.8,69.625 v2(94.8,70) 94.725,70.075 94.725,70.725 v2(94.8,70.8) v2(94,71.6) ; C13.2@95.507,73.625 95.507,73.9 v2(95.607,74) ; v2@95.607,73.999 C60.1@96.081,73.524 ; v2@95.607,75.6 95.607,75.575 95.907,75.875 C16.2@96.075,75.875 ; v2(95.625,70) 95.625,70.016 96.05,70.441 96.05,70.575 C54.2@96.075,70.6 ; C59.1@96.1,69.175 96.113,69.187 96.513,69.187 v2(96.525,69.2) ; C15.1@96.438,74.513 96.475,74.55 v2(96.475,74.85) 96.9,74.85 96.95,74.9 96.95,74.523 R262.1@97.324,74.149 ; C56.1@96.649,72.831 96.649,72.849 96.624,72.874 96.632,72.875 96.925,72.582 96.925,72.575 v2(97.125,72.375) 97.145,72.394 97.245,72.394 C58.1@97.5,72.65 ; C55.1@96.65,71.275 96.912,71.537 97.137,71.537 v2(97.175,71.575) ; v2(97.05,70) v2@97.05,70.036 ; v2@97.2,70 97.25,69.95 C53.1@97.45,69.95 ; v2(98.7,62.825) 98.7,62.835 98.85,62.985 C96.1@98.85,65 ; C63.1@100.05,64.675 C64.1@100.05,65.675 100.05,66.2 C65.1@99.925,66.325 v2@100.231,66.631 ; C180.1@108.4,88.475 108.4,89.049 108.643,89.292 108.727,89.292 v1(108.775,89.34) ; C177.1@110.35,92.025 110.425,91.95 v1(110.425,91.275) ; C173.1@110.475,70.925 110.513,70.888 110.513,69.787 C384.1@110.55,69.75 v4(110.55,68.875) ; C178.1@113.275,90.45 113.279,90.446 113.829,90.446 113.9,90.375 114.275,90.375 v1(114.3,90.35) ; v1(114.35,88.85) 115.15,88.85 C179.1@115.225,88.925 ; v4(115.9,67.545) C192.1@116.43,68.075 ; C192.1@116.5,68.075 116.675,68.25 C192.1@116.7,68.25 116.725,68.25 117.062,68.587 117.312,68.587 v4@117.35,68.625 ; v4@119.975,68.446 v4(119.975,68.5) C191.1@119.975,69.025 ; C390.1@121.551,69.002 121.563,68.99 121.563,68.512 v4(121.575,68.5) ; v4(122.075,65.8) 122.075,65.854 122.27,66.049 122.27,66.52 C194.1@122.375,66.625 ; R156.1@123.896,76.076 123.946,76.076 123.95,76.08 123.95,76.496 124,76.546 v4(124,76.6) 124.038,76.638 125.039,76.638 125.089,76.688 126.126,75.652 126.802,75.652 C143.1@126.9,75.75 126.987,75.663 126.987,75.138 v4@127.025,75.1 ; C147.1@133.75,75.525 133.775,75.5 133.775,74.9 v4@133.8,74.875 ; C146.1@135.575,75.6 135.6,75.575 135.6,74.75 v4@135.625,74.725 ; v4@136.425,74.725 C149.1@136.425,75.375 ; v4@138.025,74.725 138.062,74.763 138.062,75.337 C148.1@138.1,75.375
  other v1: 73.55,0.8 75.875,0.8 78.2,0.8 0.8,1.15 3.125,1.15 5.45,1.15 7.775,1.15 10.1,1.15 12.425,1.15 14.75,1.15 17.075,1.15 19.4,1.15 21.725,1.15 24.05,1.15 26.375,1.15 28.7,1.15 31.025,1.15 33.35,1.15 35.675,1.15 38,1.15 40.325,1.15 42.65,1.15 44.975,1.15 47.3,1.15 49.625,1.15 51.95,1.15 54.275,1.15 56.6,1.15 58.925,1.15 61.25,1.15 63.575,1.15 65.9,1.15 68.225,1.15 70.55,1.15 72.875,1.15 75.2,1.15 77.525,1.15 79.85,1.15 82.175,1.15 84.5,1.15 86.825,1.15 89.15,1.15 91.475,1.15 93.8,1.15 96.125,1.15 98.45,1.15 100.775,1.15 103.1,1.15 105.425,1.15 107.75,1.15 110.075,1.15 112.4,1.15 114.725,1.15 117.05,1.15 119.375,1.15 121.7,1.15 124.025,1.15 126.35,1.15 128.675,1.15 131,1.15 133.325,1.15 135.65,1.15 137.975,1.15 140.3,1.15 142.625,1.15 144.95,1.15 147.275,1.15 149.6,1.15 151.925,1.15 154.25,1.15 156.575,1.15 158.9,1.15 161.225,1.15 163.55,1.15 165.875,1.15 168.2,1.15 171.2,1.15 171.2,3.3 0.8,3.875 171.2,5.625 0.8,6.2 171.2,7.95 0.8,8.525 171.2,10.275 0.8,10.85 171.2,12.6 0.8,13.175 171.2,14.925 0.8,15.5 171.2,17.25 0.8,17.825 171.2,19.575 0.8,20.15 171.2,21.9 0.8,22.475 171.2,24.225 0.8,24.8 171.2,26.55 0.8,27.125 171.2,28.85 0.8,29.45 171.2,31.175 0.8,31.775 171.2,33.5 0.8,34.1 171.2,35.825 0.8,36.425 171.2,38.15 0.8,38.75 171.2,40.475 0.8,41.075 171.2,42.8 0.8,43.4 171.2,45.125 0.8,45.725 171.2,47.45 114.125,47.6 120.675,47.6 0.8,48.05 171.2,49.775 0.8,50.375 110,52.075 113.75,52.075 117.275,52.075 120.925,52.075 171.2,52.1 0.8,52.7 171.2,54.425 0.8,55.025 85.3,55.875 107.85,56.625 171.2,56.75 0.8,57.35 84.975,57.9 74.563,59.05 171.2,59.075 0.8,59.675 105,59.925 103.925,61.175 171.2,61.4 0.8,62 130.2,62.475 134.7,62.475 171.2,63.725 0.8,64.325 143.7,65.475 171.2,66.05 0.8,66.65 66.85,66.945 171.2,68.375 143.7,68.475 0.8,68.975 171.2,70.7 0.8,71.3 143.7,71.475 171.2,73.025 0.8,73.625 143.7,74.475 171.2,75.35 0.8,75.95 80.05,77.175 143.7,77.475 171.2,77.675 0.8,78.275 77.495,79.305 171.2,80 0.8,80.6 171.2,82.325 114.3,82.55 0.8,82.925 117,82.95 74.035,83.865 115.5,84.45 117,84.45 171.2,84.65 0.8,85.25 90.219,85.569 114,85.95 117,85.95 81.95,86.575 171.2,86.975 117,87.45 0.8,87.575 117,88.95 171.2,89.3 81.95,89.575 0.8,89.9 117,90.45 91.1,90.675 171.2,91.625 105,91.95 106.5,91.95 115.5,91.95 117,91.95 0.8,92.225 85.675,92.5 81.95,92.575 115.5,93.45 117,93.45 98.575,93.825 171.2,93.95 91.1,94.375 0.8,94.55 106.5,94.95 108,94.95 109.5,94.95 111,94.95 112.5,94.95 114,94.95 115.5,94.95 117,94.95 85.675,95.5 81.95,95.575 171.2,96.275 94.775,96.55 0.8,96.875 103.45,98.225 85.675,98.5 81.95,98.575 171.2,98.6 114.936,98.709 91.1,98.9 0.8,99.2 171.2,100.925 0.8,101.525 171.2,103.25 0.8,103.85 171.2,105.575 0.8,106.175 171.2,107.9 171.2,110.225 0.8,110.825 171.2,112.55 0.8,113.15 171.2,114.875 0.8,115.475 171.2,117.2 0.8,117.8 171.2,119.525 0.8,120.125 171.2,121.85 0.8,122.45 171.2,124.175 0.8,124.775 171.2,126.5 0.8,127.1 171.2,128.825 0.8,129.425 171.2,131.15 0.8,131.75 171.2,133.475 0.8,134.075 0.8,136 3.125,136.2 5.45,136.2 7.775,136.2 10.1,136.2 12.425,136.2 14.75,136.2 17.075,136.2 19.4,136.2 21.725,136.2 24.05,136.2 26.375,136.2 28.7,136.2 31.025,136.2 33.35,136.2 35.675,136.2 38,136.2 40.325,136.2 42.65,136.2 44.975,136.2 47.3,136.2 49.625,136.2 51.95,136.2 54.275,136.2 56.6,136.2 58.925,136.2 61.25,136.2 63.575,136.2 65.9,136.2 68.225,136.2 70.55,136.2 72.875,136.2 75.2,136.2 77.525,136.2 79.85,136.2 82.175,136.2 84.5,136.2 86.825,136.2 89.15,136.2 91.475,136.2 93.8,136.2 96.125,136.2 98.45,136.2 100.775,136.2 103.1,136.2 105.425,136.2 107.75,136.2 110.075,136.2 112.4,136.2 114.725,136.2 117.05,136.2 119.375,136.2 121.7,136.2 124.025,136.2 126.35,136.2 128.675,136.2 131,136.2 133.325,136.2 135.65,136.2 137.975,136.2 140.3,136.2 142.625,136.2 144.95,136.2 147.275,136.2 149.6,136.2 151.925,136.2 154.25,136.2 156.575,136.2 158.9,136.2 161.225,136.2 163.55,136.2 165.875,136.2 168.2,136.2 170.525,136.2
  other v2: 92.4,69.125 92.39,70.8 95.6,75.575 59.375,90.675 53.175,92.437
  other v3: 56.222,66.61 59.1,66.64 66.745,68.46 56.225,68.76 51.825,72.75 44.624,72.798 45.125,72.798 45.626,72.798 46.424,72.798 46.925,72.798 47.426,72.798 48.224,72.798 48.725,72.798 49.226,72.798 50.024,72.798 50.525,72.798 51.026,72.798 53.424,73.202 53.925,73.202 51.825,73.25 69.804,73.9 71.604,73.9 73.404,73.9 58.35,74.15 60,74.15 61.65,74.15 45.35,74.2 67.92,74.375 69.804,74.401 71.604,74.401 73.404,74.401 45.35,74.7 67.92,74.875 59.175,74.975 60.825,74.975 45.35,75.5 58.35,75.8 60,75.8 61.65,75.8 64.78,75.875 45.35,76 59.175,76.625 60.825,76.625 45.35,76.8 45.35,77.3 58.35,77.45 60,77.45 61.65,77.45 67.55,78.325 67.55,78.825 67.575,79.975 67.575,80.475 68.65,80.575 69.15,80.575 69.95,80.575 70.45,80.575 71.25,80.575 71.75,80.575 72.55,80.575 73.05,80.575 56.35,80.823 56.35,81.323 55.275,83.123 55.776,83.123 50.95,85.623 51.451,85.623 52.25,85.623 52.751,85.623 53.55,85.623 54.051,85.623 67.2,86.575 67.7,86.575 68.475,86.575 68.975,86.575 69.75,86.575 70.25,86.575 71.025,86.575 71.525,86.575 55.324,87.425 55.825,87.425 56.326,87.425 57.174,87.425 57.675,87.425 58.176,87.425 59.024,87.425 59.525,87.425 60.026,87.425
  other v4: 117.895,60.89 118.7,60.975 121.62,61.05 126.675,62.3 128.6,62.3 132.4,62.325 138.975,63.525 140.325,65.05 119.9,65.945 130.775,66.5 133.175,68.15 134.775,68.15 135.575,68.15 119.175,68.525 117.35,68.675 136.375,68.95 141.2,69.025 141.3,71.125 137.95,72.125 141.3,72.85 132.225,74.65 135.625,74.75 138.025,74.75 133.825,74.9 128.1,80.35 129.975,80.35 131.9,80.35 135.525,80.4
HSE_IN: C90.2 U27.V3 X2.1 | length 13.2
  Top Layer w0.1: X2.1@76.623,61.551 76.772,61.7 C90.2@77.65,61.7 78.35,61.7 81.825,65.175 83.225,65.175 85.56,67.51 86.89,67.51 U27.V3@87.2,67.2
HSE_OUT: R75.2 U27.V2 | length 12.5
  Top Layer w0.1: R75.2@77.375,59.725 77.58,59.93 77.58,60.027 78.482,60.929 78.482,61.532 81.925,64.975 83.275,64.975 83.285,64.985 83.304,64.985 85.519,67.2 U27.V2@86.4,67.2
I2C7.SCL: R261.1 U26.33 U27.F16 | length 53.8
  Top Layer w0.09: v2@97.2,76.4 U27.F16@97.6,76.8
  Top Layer w0.15: U26.33@61,78.97 61,79.5 60.85,79.65 60.85,82.813 v3(61.262,83.225)
  Bottom Layer w0.1: v3@61.268,83.22 61.268,82.625 R261.1@61.305,82.588 ; v3@61.268,83.23 61.268,83.265 61.932,83.929 62.442,83.929 65.019,86.505 65.019,87.016 69.143,91.14 86.368,91.14 96.58,80.928 96.58,76.658 96.836,76.402 v2@97.197,76.402
  other v2: 97.2,76.4
I2C7.SDA: R260.1 U26.34 U27.G15 | length 56
  Top Layer w0.09: U27.G15@96.8,76 v2(97.2,75.6)
  Top Layer w0.15: U26.34@60.6,78.97 v3(60.6,83.225)
  Bottom Layer w0.1: R260.1@60.33,82.58 60.42,82.58 60.6,82.76 v3(60.6,83.225) ; v3@60.613,83.225 61.661,84.272 62.291,84.272 64.619,86.6 64.619,87.231 68.901,91.513 86.522,91.513 97.557,80.478 97.557,75.956 v2(97.2,75.6)
MP257_WAKEUP: U26.32 U27.Y2 | length 39.9
  Top Layer w0.09: v2(85.99,65.295) 86.042,65.295 86.348,65.6 U27.Y2@86.4,65.6
  Top Layer w0.15: v3(61.3,80.4) 61.3,79.653 61.4,79.553 U26.32@61.4,78.97
  Bottom Layer w0.1: v3(61.3,80.4) 61.881,80.4 62.3,80.819 62.3,81.657 63.418,82.775 74.895,82.775 78.295,79.375 78.295,71.723 82.182,67.835 83.45,67.835 v2(85.99,65.295)
NetB2_2: B2.2 C155.2 U26.1 | length 26.2
  Top Layer w0.15: B2.2@39.882,67.292 41.271,67.292 41.933,66.63 41.933,65.666 42.532,65.067 43.658,65.067 45.208,66.618 52.086,66.618 52.59,66.114 55.417,66.114 55.696,66.393 55.696,67.818 ; 55.7,67.825 55.847,67.972 56.054,67.972 C155.2@56.227,68.145 56.062,68.31 55.838,68.31 55.687,68.46 55.687,71.008 56.462,71.783 56.462,72.237 56.855,72.63 U26.1@57.4,72.63
NetC61_2: C61.2 U27.M8 | length 1.1
  Top Layer w0.2: v2(90.8,72.4) U27.M8@91.2,72
  Bottom Layer w0.2: C61.2@90.317,72.288 90.391,72.362 90.762,72.362 v2(90.8,72.4)
NetC62_2: C62.2 R286.2 U27.T16 U27.Y16 | length 5.5
  Top Layer w0.1: U27.T16@97.6,68.8 97.6,68.425 97.1,67.925 97.1,66.1 U27.Y16@97.6,65.6 97.6,65.575 97.906,65.269 v2(97.906,65.243)
  Bottom Layer w0.2: C62.2@97.3,65.3 97.329,65.272 97.878,65.272 v2(97.906,65.243)
  Bottom Layer w0.3: R286.2@97.795,64.475 97.9,64.58 v2@97.9,65.238
NetC63_2: C63.2 C64.2 C65.2 R249.2 U27.V18 U27.V19 U27.Y19 | length 55.5
  Top Layer w0.2: U27.V18@99.2,67.2 v2(99.6,66.8) ; v2(99.6,65.2) U27.Y19@100,65.6 ; v2(99.6,66.8) U27.V19@100,67.2
  Top Layer w0.3: v2(72.351,61.252) 72.351,62.576 72.925,63.15 74.272,63.15 74.647,63.525 74.647,70.522 75.65,71.525 R249.2@75.65,74.55
  Signal Layer 4 w0.3: v2(72.351,61.252) 72.351,60.497 76.398,56.449 95.699,56.449 v2(100.025,60.775)
  Bottom Layer w0.3: v2(99.6,66.8) 99.397,66.597 99.397,66.347 C65.2@99.375,66.325 99.4,66.3 99.4,66.05 99.475,65.975 99.475,65.7 C64.2@99.5,65.675 99.5,65.326 99.6,65.227 v2(99.6,65.2) 99.6,65.173 99.5,65.073 C63.2@99.5,64.675 99.5,63.761 100.003,63.259 100.003,60.797 v2(100.025,60.775)
NetC75_2: C75.2 C79.2 R267.1 U27.V7 | length 5.7
  Top Layer w0.2: v2(90,67.6) U27.V7@90.4,67.2
  Bottom Layer w0.15: R267.1@87.25,70.375 87.675,70.375 87.925,70.125 C79.2@88.238,70.125 ; C79.2@88.3,70.125 88.238,70.063 88.238,69.738 C75.2@87.925,69.425 88.5,68.85 89.317,68.85 89.602,68.565 89.602,68.038 90,67.641 v2(90,67.6)
NetC81_1: C81.1 R64.2 X1.1 | length 2.2
  Top Layer w0.1: X1.1@76.525,67.4 78.65,67.4 R64.2@78.7,67.45
NetC88_1: C88.1 CN12.2 | length 2.1
  Top Layer w0.3: C88.1@67.475,61.3 CN12.2@67.475,63.425
NetC88_2: C88.2 D6.2 R66.2 | length 8
  Top Layer w0.3: C88.2@67.475,60.4 67.475,59.726 67.651,59.55 68.675,59.55 ; R66.2@68.675,60.395 68.675,59.55 ; D6.2@70.625,63.075 70.625,60.025 70.15,59.55 68.675,59.55
NetC91_1: C91.1 U26.7 | length 6.1
  Top Layer w0.21: U26.7@59.8,72.63 59.8,71.025 60.215,70.61 60.215,70.253
  Top Layer w0.3: v3(59.74,67.58) C91.1@60.35,67.58 ; 60.215,70.253 60.215,70.118 60.835,69.498 60.835,69.035 60.35,68.55 C91.1@60.35,67.73
NetC92_1: C92.1 R75.1 X2.3 | length 1.9
  Top Layer w0.09: X2.3@75.573,60.801 75.573,59.877 75.548,59.852 75.55,59.85 76.35,59.85 R75.1@76.475,59.725
NetC181_2: C181.2 C182.2 U24.C2 | length 3
  Top Layer w0.09: U24.C2@108.275,87.85 108.525,87.6 v1(108.525,86.8)
  Bottom Layer w0.2: C181.2@106.7,86.8 C182.2@107.825,86.8 v1(108.525,86.8)
NetC208_1: C208.1 U26.8 | length 5.4
  Top Layer w0.21: U26.8@60.2,72.63 60.2,71.134 60.625,70.709 60.625,70.345 60.798,70.173
  Top Layer w0.3: 60.798,70.173 61.3,69.67 61.3,68.843 61.175,68.718 C208.1@61.175,67.705
NetCN12_1: CN12.1 R66.1 | length 4.4
  Top Layer w0.3: CN12.1@67.475,64.675 68.344,64.675 68.675,64.344 R66.1@68.675,61.295
NetD5_1: D5.1 R248.1 U24.K5 | length 9.8
  Top Layer w0.2: v1(111.225,89.9) U24.K5@111.775,89.35
  Bottom Layer w0.1: D5.1@104.175,88.63 104.995,88.63 105.675,87.95 R248.1@110.775,87.95
  Bottom Layer w0.3: R248.1@110.775,87.95 110.775,89.45 v1(111.225,89.9)
NetD6_1: D6.1 R67.1 | length 1.4
  Top Layer w0.3: D6.1@70.625,64.975 R67.1@70.625,66.375
NetL1_1: L1.1 U26.37 | length 4.2
  Top Layer w0.21: U26.37@59.4,78.97 59.4,79.525
  Top Layer w0.25: L1.1@59.2,83.135 59.2,80.173 59.4,79.973 59.4,79.525
NetL2_1: L2.1 U26.26 | length 4.1
  Top Layer w0.2: U26.26@63.417,77.6 63.9,77.6 64.225,77.925 64.225,80.56 ; L2.1@65.35,81.685 L2.1@65.35,82.2
NetL3_1: L3.1 U26.40 | length 5.9
  Top Layer w0.15: L3.1@53.198,80.162 L3.1@53.35,80.01
  Top Layer w0.21: L3.1@53.35,80.275 53.635,79.99 55.41,79.99 57.765,79.99 58.2,79.555 U26.40@58.2,78.97
NetL4_1: L4.1 U26.23 | length 3.8
  Top Layer w0.15: L4.1@66.86,75.885 L4.1@66.86,76.4
  Top Layer w0.21: U26.23@63.17,76.4 63.725,76.4
  Top Layer w0.25: 63.725,76.4 66.5,76.4
NetL5_1: L5.1 U26.48 | length 7.2
  Top Layer w0.15: L5.1@51.118,74.448 L5.1@51.37,74.7 ; L5.1@51.59,74.585 L5.1@51.59,75.1
  Top Layer w0.21: 56.275,76.4 U26.48@56.83,76.4
  Top Layer w0.25: 51.325,75.6 51.775,76.05 54.7,76.05 55.05,76.4 56.275,76.4 ; L5.1@51.59,75.1 51.59,75.615
NetL6_1: L6.1 U26.19 | length 4.9
  Top Layer w0.21: U26.19@63.17,74.8 63.725,74.8
  Top Layer w0.25: 63.725,74.8 64.123,74.8 64.298,74.625 64.65,74.625 64.875,74.4 64.875,73.325 65.571,72.629 65.925,72.629 65.93,72.624 L6.1@65.93,72.025
NetL7_1: L7.1 U26.51 | length 7.4
  Top Layer w0.21: 56.275,75.2 U26.51@56.83,75.2
  Top Layer w0.25: L7.1@53.925,70.425 L7.1@53.925,70.669 ; L7.1@53.975,69.95 54.375,70.35 54.375,72.184 54.85,72.659 54.85,74.503 55.547,75.2 56.275,75.2
NetLD11_1: LD11.1 R210.2 | length 1
  Top Layer w0.2: LD11.1@42.887,68.077 R210.2@42.887,69.07
NetR2_2: R2.2 U26.56 | length 6.1
  Top Layer w0.15: R2.2@55.08,68.145 55.08,68.76 55.375,69.055 55.375,71.091 56.012,71.728 56.012,72.985 56.227,73.2 U26.56@56.755,73.2
NetR46_2: R46.2 U26.30 | length 2.8
  Top Layer w0.15: U26.30@62.2,78.97 62.2,80.87 62.532,81.202 62.532,81.43 R46.2@62.65,81.548
NetR57_2: R57.2 U26.12 | length 4.9
  Top Layer w0.21: U26.12@61.8,72.63 61.8,72.016 61.97,71.845
  Top Layer w0.3: 61.97,71.845 62.525,71.291 62.525,70.174 63.35,69.349 R57.2@63.35,68.4
NetR59_2: R59.2 U26.54 | length 8.5
  Top Layer w0.15: R59.2@52.98,68.145 52.98,68.64 53.15,68.81 54.236,68.81 54.875,69.449 54.875,71.298 55.512,71.935 55.512,73.335 56.177,74 U26.54@56.83,74
NetR60_2: R60.2 U26.55 | length 7.1
  Top Layer w0.15: R60.2@54.03,68.145 54.104,68.145 55.125,69.166 55.125,71.194 55.762,71.832 55.762,73.232 56.131,73.6 U26.55@56.83,73.6
NetR68_2: R68.2 U14.L8 | length 3.9
  Top Layer w0.09: U14.L8@131.175,68.55 131.575,68.15 132.1,68.15 132.325,67.925 132.325,67.5 133.175,66.65 R68.2@133.175,65.775
NetR81_2: R81.2 U26.31 | length 5.7
  Top Layer w0.15: U26.31@61.8,78.97 61.8,80.973 61.95,81.123 61.95,83.81 62.038,83.898 R81.2@62.663,83.898
NetR83_2: R83.2 U16.L8 | length 3.7
  Top Layer w0.15: U16.L8@114.701,62.327 115.101,61.927 115.773,61.927 115.91,61.79 115.91,59.593 R83.2@115.951,59.552
NetR262_2: R262.2 U27.K16 | length 1.4
  Top Layer w0.09: U27.K16@97.6,73.6 v5(98,73.2)
  Bottom Layer w0.09: R262.2@97.924,74.149 R262.2@97.978,74.096
  Bottom Layer w0.2: v5@97.978,73.3 R262.2@97.978,74.096
NetTP9_1: TP9.1 U24.H5 | length 7.4
  Top Layer w0.09: 110.525,87 110.525,88.468 110.775,88.718 U24.H5@110.775,89.35
  Top Layer w0.11: 110.525,87 110.775,86.75 112.106,86.75 112.43,86.426 TP9.1@112.43,83.629
NRST: C33.2 R81.1 U27.U3 | length 51
  Top Layer w0.09: 82.437,66.05 84.398,68.011 87.189,68.011 U27.U3@87.2,68
  Top Layer w0.1: v2@75.425,70.347 C33.2@75.425,69.775 75.4,69.775 75.195,69.57 75.195,69.544 74.971,69.32 74.971,64.793 75.534,64.23 79.62,64.23 81.44,66.05 82.437,66.05
  Top Layer w0.15: v2(62.651,85.672) 62.663,85.661 R81.1@62.663,84.798
  Bottom Layer w0.1: v2(62.651,85.672) 62.644,85.679 60.373,85.679 59.159,84.466 59.159,80.601 61.914,77.847 68.567,77.847 71.354,75.06 74.014,75.06 75.433,73.641 75.433,70.356 v2(75.424,70.347)
NRSTC1MS: D5.2 R27.1 R59.1 R272.1 U27.T3 | length 120.3
  Top Layer w0.09: v2(82.345,67.035) 82.859,67.035 84.03,68.206 86.216,68.206 86.49,68.48 86.88,68.48 U27.T3@87.2,68.8
  Top Layer w0.1: R59.1@52.98,67.245 52.988,67.237 v1@52.988,66.633 ; v2(72.425,66.05) 72.45,66.025 R27.1@73.125,66.025 ; v2(76.475,80.475) 79.028,83.028 v2@79.028,105.328
  Bottom Layer w0.1: R272.1@53.025,65.879 53.025,66.621 v1(52.983,66.663) 53.492,67.172 56.612,67.172 57.799,65.986 72.361,65.986 v2(72.425,66.05) 72.489,65.986 81.296,65.986 v2(82.345,67.035) 81.19,67.035 77.64,70.585 77.64,78.455 76.475,79.62 v2(76.475,80.475) ; v2@79.024,105.399 82.75,109.125 94.793,109.125 104.175,99.743 D5.2@104.175,90.77
  other v2: 79.033,105.377
OSC32_IN: C86.1 U27.R1 X1.2 | length 12.2
  Top Layer w0.09: C86.1@77.85,65.9 77.85,66.725 78,66.875 79.835,66.875 80,67.04 80,68.544 80.444,68.988 82.817,68.988 83.735,69.905 85.295,69.905 U27.R1@85.6,69.6
  Top Layer w0.1: X1.2@76.525,65.9 C86.1@77.85,65.9
OSC32_OUT: R64.1 U27.R2 | length 8.7
  Top Layer w0.09: R64.1@79.6,67.45 79.6,68.413 80.365,69.178 81.172,69.178 ; 81.172,69.175 82.75,69.175 83.66,70.085 85.532,70.085 86.017,69.6 U27.R2@86.4,69.6
PMIC_WAKEUPn: R46.1 U27.P6 | length 38.7
  Top Layer w0.09: v2(82.54,68.284) 82.555,68.298 83.068,68.298 83.983,69.212 85.187,69.212 85.289,69.315 87.318,69.315 87.332,69.315 87.495,69.478 87.495,69.492 87.705,69.702 87.705,69.722 87.878,69.895 87.898,69.895 87.899,69.896 87.899,69.9 88.371,69.9 88.546,70.075 89.275,70.075 U27.P6@89.6,70.4
  Top Layer w0.15: R46.1@62.65,82.448 v3(62.65,83.033)
  Bottom Layer w0.1: v3@62.703,83.022 75.078,83.022 78.559,79.541 78.559,72.368 82.444,68.482 82.444,68.461 82.54,68.365 v2(82.54,68.284)
PWR_CPU_ON: R60.1 R272.2 U27.T6 | length 42.5
  Top Layer w0.1: v1@54.014,66.64 54.014,67.229 R60.1@54.03,67.245 ; U27.T6@89.6,68.8 v2(90,68.4)
  Bottom Layer w0.1: R272.2@53.925,65.879 54.456,65.879 54.785,65.55 68.85,65.55 70.209,64.191 88.964,64.191 90.107,65.334 90.107,67.029 90.425,67.348 90.425,67.975 v2(90,68.4) ; R272.2@53.991,66.065 53.991,66.652 v1(54.009,66.67)
PWR_ON: R2.1 U27.T5 | length 39.8
  Top Layer w0.1: v1@55.08,66.64 R2.1@55.08,67.245 ; U27.T5@88.8,68.8 v2(89.2,68.4)
  Bottom Layer w0.1: v1(55.075,66.67) 55.119,66.67 56.017,65.772 69.502,65.772 70.717,64.558 75.903,64.558 76.287,64.942 88.706,64.942 89.615,65.85 89.615,67.702 89.206,68.111 89.206,68.394 v2(89.2,68.4)
VBAT: C87.2 D6.3 U27.P7 | length 24
  Top Layer w0.2: v2(90.019,69.225) 90.025,69.231 90.025,69.25 90.006,69.269 90.006,70.006 U27.P7@90.4,70.4
  Top Layer w0.3: D6.3@73.2,64.375 72.85,64.025 D6.3@72.825,64.025 73.188,64.388 73.825,65.025 C87.2@74.05,65.025 ; C87.2@73.925,65.125 74.17,65.125 74.175,65.13 v2(74.175,68.35)
  Signal Layer 4 w0.2: v2(74.175,68.35) 74.175,68.325 74.718,67.782 84.157,67.782 84.575,68.2 85.215,68.2 85.426,67.989 88.555,67.989 88.8,68.234 88.8,68.566 89.035,68.8 89.296,68.8 89.596,69.1 89.84,69.1 89.965,69.225 v2(90.019,69.225)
